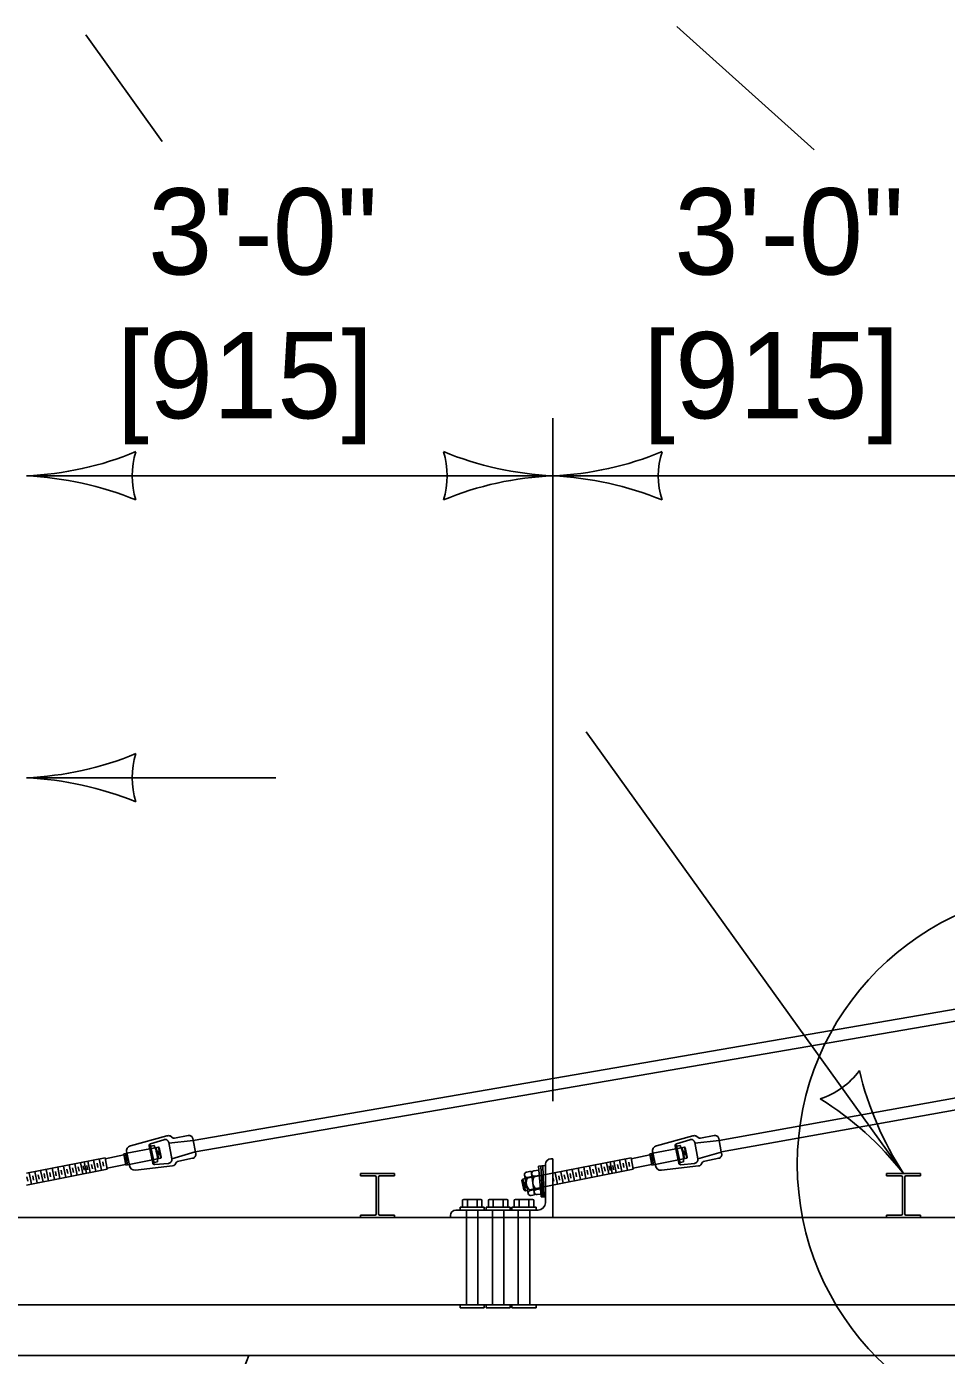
# Model space of a CAD drawing. Extents: x 49991.4 to 50021, y 49987.6 to 50011.4.
# Drawn here: x 50002.768 to 50003.408, y 49996.713 to 49997.638 of the extents above; entities that cross this region are included whole.
import ezdxf

# ---------------------------------------------------------------- set-up
doc = ezdxf.new("R2010")
doc.units = 0
for name, color, linetype in [('Level 1', 7, 'Continuous'), ('Level 2', 7, 'Continuous'), ('Level 3', 7, 'Continuous'), ('Level 4', 7, 'Continuous')]:
    doc.layers.add(name, color=color, linetype=linetype)

msp = doc.modelspace()

# ---------------------------------------------------------------- linework, layer by layer
at = {"layer": 'Level 1'}
for p, q in [((50002.8842, 49996.86275), (50006.12112, 49997.4208)), ((50002.88578, 49996.85474), (50006.12265, 49997.41281)), ((50003.25008, 49996.86273), (50006.12834, 49997.38128)), ((50003.25178, 49996.85474), (50006.1298, 49997.37361)), ((50002.86593, 49996.86597), (50002.84073, 49996.85901)), ((50002.85466, 49996.85945), (50002.85372, 49996.85927)), ((50002.85614, 49996.84702), (50002.85378, 49996.85897)), ((50002.85466, 49996.85945), (50002.85726, 49996.84691)), ((50002.86384, 49996.86331), (50002.85469, 49996.86047)), ((50002.85709, 49996.85931), (50002.85479, 49996.85886)), ((50002.86948, 49996.85002), (50002.86727, 49996.86126)), ((50002.87043, 49996.8644), (50002.86817, 49996.86592)), ((50002.88079, 49996.86617), (50002.87123, 49996.86428)), ((50002.88394, 49996.86406), (50002.88602, 49996.85355)), ((50003.23181, 49996.86595), (50003.20661, 49996.85898)), ((50003.22054, 49996.85943), (50003.2196, 49996.85925)), ((50003.22201, 49996.847), (50003.21965, 49996.85895)), ((50003.22054, 49996.85943), (50003.22314, 49996.84689)), ((50003.22971, 49996.86329), (50003.22057, 49996.86045)), ((50003.22296, 49996.85929), (50003.22066, 49996.85883)), ((50003.23536, 49996.85), (50003.23315, 49996.86124)), ((50003.23631, 49996.86438), (50003.23404, 49996.8659)), ((50003.24666, 49996.86615), (50003.2371, 49996.86426)), ((50003.24982, 49996.86404), (50003.25189, 49996.85352)), ((50002.7684, 49996.83992), (50002.82299, 49996.85071)), ((50002.81498, 49996.84913), (50002.81666, 49996.84126)), ((50002.81892, 49996.8499), (50002.82048, 49996.84202)), ((50002.82299, 49996.85071), (50002.82455, 49996.84282)), ((50002.83612, 49996.85268), (50002.82313, 49996.84999)), ((50002.83823, 49996.85385), (50002.83599, 49996.85341)), ((50002.83599, 49996.85341), (50002.83741, 49996.84561)), ((50002.83713, 49996.85077), (50002.83775, 49996.84828)), ((50002.8386, 49996.84585), (50002.83719, 49996.85364)), ((50002.8381, 49996.85449), (50002.83998, 49996.8453)), ((50002.83832, 49996.85101), (50002.8388, 49996.84862)), ((50002.8601, 49996.85817), (50002.85781, 49996.85771)), ((50002.85852, 49996.85786), (50002.86019, 49996.85012)), ((50002.86176, 49996.85042), (50002.85946, 49996.84997)), ((50002.85963, 49996.85563), (50002.86029, 49996.85257)), ((50002.86068, 49996.85778), (50002.8601, 49996.85817)), ((50002.86176, 49996.85042), (50002.8601, 49996.85817)), ((50002.86068, 49996.85778), (50002.86209, 49996.85123)), ((50002.86209, 49996.85123), (50002.86176, 49996.85042)), ((50002.88393, 49996.85039), (50002.87428, 49996.84838)), ((50003.1344, 49996.85004), (50003.13312, 49996.85004)), ((50003.13428, 49996.8399), (50003.18887, 49996.85069)), ((50003.1344, 49996.85004), (50003.1344, 49996.80924)), ((50003.18086, 49996.8491), (50003.18254, 49996.84124)), ((50003.1848, 49996.84988), (50003.18636, 49996.842)), ((50003.18887, 49996.85069), (50003.19042, 49996.8428)), ((50003.202, 49996.85266), (50003.18901, 49996.84997)), ((50003.2041, 49996.85383), (50003.20187, 49996.85338)), ((50003.20187, 49996.85338), (50003.20328, 49996.84559)), ((50003.20301, 49996.85075), (50003.20362, 49996.84826)), ((50003.20448, 49996.84583), (50003.20307, 49996.85362)), ((50003.20397, 49996.85447), (50003.20585, 49996.84527)), ((50003.2042, 49996.85098), (50003.20467, 49996.84859)), ((50003.22598, 49996.85815), (50003.22368, 49996.85769)), ((50003.2244, 49996.85783), (50003.22607, 49996.85009)), ((50003.22764, 49996.8504), (50003.22533, 49996.84995)), ((50003.2255, 49996.85561), (50003.22617, 49996.85255)), ((50003.22655, 49996.85776), (50003.22598, 49996.85815)), ((50003.22764, 49996.8504), (50003.22598, 49996.85815)), ((50003.22655, 49996.85776), (50003.22797, 49996.85121)), ((50003.22797, 49996.85121), (50003.22764, 49996.8504)), ((50003.24981, 49996.85037), (50003.24015, 49996.84836)), ((50002.7684, 49996.83173), (50002.82455, 49996.84282)), ((50002.77029, 49996.8403), (50002.77185, 49996.83241)), ((50002.77423, 49996.84108), (50002.77579, 49996.83319)), ((50002.77817, 49996.84185), (50002.77985, 49996.83399)), ((50002.78212, 49996.84263), (50002.78368, 49996.83475)), ((50002.78464, 49996.84053), (50002.78512, 49996.83751)), ((50002.78618, 49996.84344), (50002.78774, 49996.83555)), ((50002.78847, 49996.84128), (50002.78909, 49996.83818)), ((50002.79012, 49996.84421), (50002.79157, 49996.8363)), ((50002.79253, 49996.84209), (50002.793, 49996.83908)), ((50002.79407, 49996.84499), (50002.79563, 49996.83711)), ((50002.79636, 49996.84284), (50002.79707, 49996.83987)), ((50002.79801, 49996.84577), (50002.79957, 49996.83789)), ((50002.80042, 49996.84364), (50002.80104, 49996.84054)), ((50002.80196, 49996.84655), (50002.80352, 49996.83867)), ((50002.80425, 49996.84439), (50002.80495, 49996.84144)), ((50002.8059, 49996.84733), (50002.80758, 49996.83947)), ((50002.80783, 49996.8451), (50002.80844, 49996.842)), ((50002.80853, 49996.84785), (50002.80997, 49996.83994)), ((50002.81026, 49996.84534), (50002.81074, 49996.84233)), ((50002.81104, 49996.84835), (50002.81259, 49996.84046)), ((50002.81347, 49996.8461), (50002.81418, 49996.84313)), ((50002.81739, 49996.84699), (50002.818, 49996.84389)), ((50002.82145, 49996.84779), (50002.82192, 49996.84478)), ((50002.83732, 49996.84609), (50002.82441, 49996.84354)), ((50002.83981, 49996.84609), (50002.83741, 49996.84561)), ((50002.86994, 49996.84503), (50002.84408, 49996.84203)), ((50002.85726, 49996.84691), (50002.85625, 49996.84671)), ((50002.85944, 49996.84798), (50002.85713, 49996.84752)), ((50002.86709, 49996.84682), (50002.85758, 49996.84594)), ((50002.87149, 49996.8458), (50002.87272, 49996.84764)), ((50003.11621, 49996.84068), (50003.11946, 49996.84133)), ((50003.12166, 49996.82489), (50003.11946, 49996.84133)), ((50003.12127, 49996.84156), (50003.12475, 49996.84203)), ((50003.12449, 49996.84487), (50003.12919, 49996.84543)), ((50003.12449, 49996.84487), (50003.12645, 49996.82355)), ((50003.12611, 49996.84507), (50003.1273, 49996.82358)), ((50003.12757, 49996.84524), (50003.12822, 49996.8236)), ((50003.12932, 49996.84624), (50003.12932, 49996.8194)), ((50003.13428, 49996.83171), (50003.19042, 49996.8428)), ((50003.13617, 49996.84028), (50003.13772, 49996.83239)), ((50003.1401, 49996.84105), (50003.14166, 49996.83317)), ((50003.14405, 49996.84183), (50003.14573, 49996.83397)), ((50003.14799, 49996.84261), (50003.14955, 49996.83472)), ((50003.15052, 49996.84051), (50003.15099, 49996.83749)), ((50003.15206, 49996.84341), (50003.15361, 49996.83553)), ((50003.15434, 49996.84126), (50003.15496, 49996.83815)), ((50003.156, 49996.84419), (50003.15744, 49996.83628)), ((50003.15841, 49996.84207), (50003.15888, 49996.83905)), ((50003.15994, 49996.84497), (50003.1615, 49996.83709)), ((50003.16223, 49996.84282), (50003.16295, 49996.83985)), ((50003.16389, 49996.84575), (50003.16544, 49996.83786)), ((50003.16629, 49996.84362), (50003.16691, 49996.84051)), ((50003.16783, 49996.84653), (50003.16939, 49996.83865)), ((50003.17012, 49996.84437), (50003.17083, 49996.84141)), ((50003.17178, 49996.84731), (50003.17345, 49996.83945)), ((50003.17371, 49996.84508), (50003.17432, 49996.84198)), ((50003.17441, 49996.84783), (50003.17584, 49996.83992)), ((50003.17614, 49996.84532), (50003.17661, 49996.84231)), ((50003.17692, 49996.84833), (50003.17847, 49996.84044)), ((50003.17935, 49996.84608), (50003.18006, 49996.84311)), ((50003.18327, 49996.84697), (50003.18388, 49996.84387)), ((50003.18733, 49996.84777), (50003.1878, 49996.84476)), ((50003.2032, 49996.84607), (50003.19029, 49996.84352)), ((50003.20569, 49996.84607), (50003.20328, 49996.84559)), ((50003.23582, 49996.84501), (50003.20996, 49996.84201)), ((50003.22314, 49996.84689), (50003.22212, 49996.84669)), ((50003.22531, 49996.84796), (50003.22301, 49996.8475)), ((50003.23297, 49996.8468), (50003.22346, 49996.84592)), ((50003.23737, 49996.84578), (50003.2386, 49996.84762)), ((50002.76863, 49996.83737), (50002.76934, 49996.8344)), ((50002.77269, 49996.83817), (50002.77317, 49996.83515)), ((50002.77652, 49996.83892), (50002.77723, 49996.83595)), ((50002.78058, 49996.83973), (50002.7812, 49996.83662)), ((50003.02424, 49996.83972), (50003.00056, 49996.83972)), ((50003.00056, 49996.83812), (50003.00056, 49996.83972)), ((50003.0108, 49996.83812), (50003.00056, 49996.83812)), ((50003.0116, 49996.81164), (50003.0116, 49996.83732)), ((50003.0132, 49996.81164), (50003.0132, 49996.83732)), ((50003.02424, 49996.83812), (50003.014, 49996.83812)), ((50003.02424, 49996.83812), (50003.02424, 49996.83972)), ((50003.113, 49996.83495), (50003.11368, 49996.83595)), ((50003.11427, 49996.82849), (50003.113, 49996.83494)), ((50003.11368, 49996.83595), (50003.11524, 49996.83626)), ((50003.11368, 49996.83595), (50003.11542, 49996.82773)), ((50003.11466, 49996.82968), (50003.11371, 49996.83385)), ((50003.11735, 49996.82591), (50003.11477, 49996.83854)), ((50003.11576, 49996.82978), (50003.11506, 49996.83399)), ((50003.11692, 49996.83711), (50003.11995, 49996.83771)), ((50003.12176, 49996.83794), (50003.12509, 49996.83838)), ((50003.13451, 49996.83734), (50003.13522, 49996.83437)), ((50003.13857, 49996.83815), (50003.13904, 49996.83513)), ((50003.14239, 49996.8389), (50003.14311, 49996.83593)), ((50003.14646, 49996.8397), (50003.14707, 49996.8366)), ((50003.39024, 49996.83972), (50003.36656, 49996.83972)), ((50003.36656, 49996.83812), (50003.36656, 49996.83972)), ((50003.3768, 49996.83812), (50003.36656, 49996.83812)), ((50003.3776, 49996.81164), (50003.3776, 49996.83732)), ((50003.3792, 49996.81164), (50003.3792, 49996.83732)), ((50003.39024, 49996.83812), (50003.38, 49996.83812)), ((50003.39024, 49996.83812), (50003.39024, 49996.83972)), ((50003.07163, 49996.8166), (50003.07163, 49996.82149)), ((50003.07333, 49996.82177), (50003.08346, 49996.82177)), ((50003.07499, 49996.81659), (50003.07499, 49996.8215)), ((50003.08182, 49996.81659), (50003.08182, 49996.8215)), ((50003.08517, 49996.8166), (50003.08517, 49996.82149)), ((50003.08963, 49996.8166), (50003.08963, 49996.82149)), ((50003.09133, 49996.82177), (50003.10146, 49996.82177)), ((50003.09299, 49996.81659), (50003.09299, 49996.8215)), ((50003.09982, 49996.81659), (50003.09982, 49996.8215)), ((50003.10317, 49996.8166), (50003.10317, 49996.82149)), ((50003.10763, 49996.8166), (50003.10763, 49996.82149)), ((50003.10933, 49996.82177), (50003.11946, 49996.82177)), ((50003.11099, 49996.81659), (50003.11099, 49996.8215)), ((50003.11542, 49996.82773), (50003.11427, 49996.82849)), ((50003.11542, 49996.82773), (50003.11692, 49996.82803)), ((50003.11782, 49996.81659), (50003.11782, 49996.8215)), ((50003.11879, 49996.82805), (50003.12118, 49996.82852)), ((50003.1195, 49996.82447), (50003.12166, 49996.82489)), ((50003.12117, 49996.8166), (50003.12117, 49996.82149)), ((50003.12299, 49996.82876), (50003.12594, 49996.82916)), ((50003.12348, 49996.82514), (50003.12627, 49996.82551)), ((50003.12645, 49996.82355), (50003.12932, 49996.82363)), ((50003.12424, 49996.81432), (50003.067, 49996.81432)), ((50003.07001, 49996.81632), (50003.08679, 49996.81632)), ((50003.07001, 49996.81632), (50003.07001, 49996.81432)), ((50003.07001, 49996.81432), (50003.08679, 49996.81432)), ((50003.08679, 49996.81632), (50003.08679, 49996.81432)), ((50003.08801, 49996.81632), (50003.10479, 49996.81632)), ((50003.08801, 49996.81632), (50003.08801, 49996.81432)), ((50003.08801, 49996.81432), (50003.10479, 49996.81432)), ((50003.10479, 49996.81632), (50003.10479, 49996.81432)), ((50003.10601, 49996.81632), (50003.12279, 49996.81632)), ((50003.10601, 49996.81632), (50003.10601, 49996.81432)), ((50003.10601, 49996.81432), (50003.12279, 49996.81432)), ((50003.12279, 49996.81632), (50003.12279, 49996.81432)), ((50004.83228, 49996.80924), (50002.6464, 49996.80924)), ((50003.00056, 49996.80924), (50003.00056, 49996.81084)), ((50003.0108, 49996.81084), (50003.00056, 49996.81084)), ((50003.02424, 49996.81084), (50003.014, 49996.81084)), ((50003.02424, 49996.80924), (50003.02424, 49996.81084)), ((50003.0632, 49996.80924), (50003.0632, 49996.81052)), ((50003.1344, 49996.80924), (50003.0632, 49996.80924)), ((50003.3768, 49996.81084), (50003.36656, 49996.81084)), ((50003.36656, 49996.81084), (50003.36656, 49996.80924)), ((50003.39024, 49996.81084), (50003.38, 49996.81084)), ((50003.39024, 49996.80924), (50003.39024, 49996.81084)), ((50003.86643, 49996.74844), (50000.13627, 49996.74844)), ((50003.9076, 49996.71324), (50000.15294, 49996.71324))]:
    msp.add_line(p, q, dxfattribs=at)
msp.add_circle((50003.49532, 49996.84624), 0.19084, dxfattribs=at)
for centre, radius, start, end in [((50002.84143, 49996.85557), 0.0035, 101.46836, 197.94993), ((50002.85488, 49996.85933), 0.00116, 99.58417, 197.7734), ((50002.8368, 49996.84919), 0.02267, 356.92883, 26.50774), ((50002.86476, 49996.86096), 0.00252, 6.78065, 111.49404), ((50002.86698, 49996.86272), 0.00341, 69.60327, 107.90821), ((50002.87104, 49996.86575), 0.00148, 245.81175, 277.18979), ((50002.88141, 49996.86369), 0.00256, 8.29576, 104.05253), ((50003.2073, 49996.85555), 0.0035, 101.46836, 197.94993), ((50003.22076, 49996.85931), 0.00116, 99.58417, 197.7734), ((50003.20268, 49996.84917), 0.02267, 356.92883, 26.50774), ((50003.23064, 49996.86094), 0.00252, 6.78065, 111.49404), ((50003.23286, 49996.8627), 0.00341, 69.60327, 107.90821), ((50003.23692, 49996.86573), 0.00148, 245.81175, 277.18979), ((50003.24728, 49996.86367), 0.00256, 8.29576, 104.05253), ((50002.86678, 49996.84955), 0.00274, 276.48423, 9.91066), ((50002.88345, 49996.85297), 0.00263, 280.42161, 12.59648), ((50003.13312, 49996.84624), 0.0038, 90, 180), ((50003.23266, 49996.84953), 0.00274, 276.48423, 9.91066), ((50003.24933, 49996.85295), 0.00263, 280.42161, 12.59648), ((50002.84392, 49996.84604), 0.00401, 190.70039, 272.37573), ((50002.85749, 49996.84732), 0.00138, 192.45537, 273.81412), ((50002.86992, 49996.84701), 0.00198, 270.62889, 322.54343), ((50002.87428, 49996.84639), 0.002, 90.00489, 141.0233), ((50003.11656, 49996.8389), 0.00183, 101.17557, 281.17272), ((50003.12152, 49996.83975), 0.00183, 97.63348, 277.63063), ((50003.20979, 49996.84602), 0.00401, 190.70039, 272.37573), ((50003.22337, 49996.8473), 0.00138, 192.45537, 273.81412), ((50003.2358, 49996.84699), 0.00198, 270.62889, 322.54343), ((50003.24015, 49996.84637), 0.002, 90.00489, 141.0233), ((50003.0108, 49996.83732), 0.0008, 0, 90), ((50003.014, 49996.83732), 0.0008, 90, 180), ((50003.12279, 49996.83356), 0.00686, 148.88147, 233.6485), ((50003.12729, 49996.83401), 0.00679, 144.59653, 230.66757), ((50003.3768, 49996.83732), 0.0008, 0, 90), ((50003.38, 49996.83732), 0.0008, 90, 180), ((50003.11914, 49996.82626), 0.00183, 101.17557, 281.17272), ((50003.12323, 49996.82695), 0.00183, 97.63348, 277.63063), ((50003.067, 49996.81052), 0.0038, 90, 180), ((50003.12424, 49996.8194), 0.00508, 270, 0), ((50003.0108, 49996.81164), 0.0008, 270, 0), ((50003.014, 49996.81164), 0.0008, 180, 270), ((50003.3768, 49996.81164), 0.0008, 270, 0), ((50003.38, 49996.81164), 0.0008, 180, 270)]:
    msp.add_arc(centre, radius, start, end, dxfattribs=at)
for centre, major_axis, start_param, end_param in [((50003.07332, 49996.81966), (0.00339, 0), 1.056847, 2.094396), ((50003.0784, 49996.81332), (0.01355, 0), 1.315951, 1.825641), ((50003.08348, 49996.81966), (0.00339, 0), 1.047198, 2.084746), ((50003.09132, 49996.81966), (0.00339, 0), 1.056847, 2.094396), ((50003.0964, 49996.81332), (0.01355, 0), 1.315951, 1.825641), ((50003.10148, 49996.81966), (0.00339, 0), 1.047198, 2.084746), ((50003.10932, 49996.81966), (0.00339, 0), 1.056847, 2.094396), ((50003.1144, 49996.81332), (0.01355, 0), 1.315951, 1.825641), ((50003.11948, 49996.81966), (0.00339, 0), 1.047198, 2.084746), ((50003.07332, 49996.81843), (0.00339, 0), 4.188789, 5.226338), ((50003.0784, 49996.82477), (0.01355, 0), 4.457545, 4.967235), ((50003.08348, 49996.81843), (0.00339, 0), 4.198439, 5.235988), ((50003.09132, 49996.81843), (0.00339, 0), 4.188789, 5.226338), ((50003.0964, 49996.82477), (0.01355, 0), 4.457545, 4.967235), ((50003.10148, 49996.81843), (0.00339, 0), 4.198439, 5.235988), ((50003.10932, 49996.81843), (0.00339, 0), 4.188789, 5.226338), ((50003.1144, 49996.82477), (0.01355, 0), 4.457545, 4.967235), ((50003.11948, 49996.81843), (0.00339, 0), 4.198439, 5.235988)]:
    msp.add_ellipse(centre, major_axis=major_axis, ratio=0.623816, start_param=start_param, end_param=end_param, dxfattribs=at)
at = {"layer": 'Level 3'}
for p, q in [((50003.22069, 49997.63753), (50003.31634, 49997.55177)), ((50002.80952, 49997.63175), (50002.86281, 49997.55755)), ((50003.1344, 49996.89004), (50003.1344, 49997.36506)), ((50002.7684, 49997.32506), (50003.1344, 49997.32506)), ((50003.1344, 49997.32506), (50003.5004, 49997.32506)), ((50003.15774, 49997.14694), (50003.3784, 49996.83972)), ((50002.7684, 49997.11506), (50002.94184, 49997.11506)), ((50002.9231, 49996.71324), (50002.81609, 49996.44087))]:
    msp.add_line(p, q, dxfattribs=at)
for centre, radius, start, end in [((50002.75924, 49997.5472), 0.22232, 272.36048, 292.54399), ((50002.89661, 49997.32506), 0.05477, 162.13882, 197.86118), ((50003.00619, 49997.32506), 0.05477, 342.13882, 17.86118), ((50003.14589, 49997.55778), 0.233, 247.92284, 267.17269), ((50003.12524, 49997.5472), 0.22232, 272.36048, 292.54399), ((50003.26261, 49997.32506), 0.05477, 162.13882, 197.86118), ((50002.75691, 49997.09235), 0.233, 67.92284, 87.17269), ((50003.14356, 49997.10293), 0.22232, 92.36048, 112.54399), ((50003.12291, 49997.09235), 0.233, 67.92284, 87.17269), ((50002.75924, 49997.3372), 0.22232, 272.36048, 292.54399), ((50002.89661, 49997.11506), 0.05477, 162.13882, 197.86118), ((50002.75691, 49996.88235), 0.233, 67.92284, 87.17269), ((50003.3036, 49996.94386), 0.05477, 287.82673, 323.54909), ((50003.57412, 49996.96614), 0.233, 193.61075, 212.8606), ((50003.20332, 49996.7027), 0.22232, 38.04839, 58.2319)]:
    msp.add_arc(centre, radius, start, end, dxfattribs=at)
at = {"layer": 'Level 4'}
for p, q in [((50002.8842, 49996.86275), (50002.86735, 49996.86087)), ((50003.25008, 49996.86273), (50003.23322, 49996.86085)), ((50002.85781, 49996.85771), (50002.83823, 49996.85385)), ((50002.85946, 49996.84997), (50002.83981, 49996.84609)), ((50002.88578, 49996.85474), (50002.86947, 49996.85006)), ((50003.22368, 49996.85769), (50003.2041, 49996.85383)), ((50003.22533, 49996.84995), (50003.20569, 49996.84607)), ((50003.25166, 49996.85472), (50003.23535, 49996.85004)), ((50003.13428, 49996.8399), (50003.11636, 49996.83648)), ((50003.11834, 49996.82834), (50003.13428, 49996.83171)), ((50003.0744, 49996.74844), (50003.0744, 49996.81432)), ((50003.0824, 49996.74844), (50003.0824, 49996.81432)), ((50003.0924, 49996.74844), (50003.0924, 49996.81432)), ((50003.1004, 49996.74844), (50003.1004, 49996.81432)), ((50003.1104, 49996.74844), (50003.1104, 49996.81432)), ((50003.1184, 49996.74844), (50003.1184, 49996.81432)), ((50003.07001, 49996.74645), (50003.07001, 49996.74844)), ((50003.07001, 49996.74844), (50003.08679, 49996.74844)), ((50003.08679, 49996.74645), (50003.08679, 49996.74844)), ((50003.08801, 49996.74645), (50003.08801, 49996.74844)), ((50003.08801, 49996.74844), (50003.10479, 49996.74844)), ((50003.10479, 49996.74645), (50003.10479, 49996.74844)), ((50003.10601, 49996.74645), (50003.10601, 49996.74844)), ((50003.10601, 49996.74844), (50003.12279, 49996.74844)), ((50003.12279, 49996.74645), (50003.12279, 49996.74844)), ((50003.07001, 49996.74645), (50003.08679, 49996.74645)), ((50003.08801, 49996.74645), (50003.10479, 49996.74645)), ((50003.10601, 49996.74645), (50003.12279, 49996.74645))]:
    msp.add_line(p, q, dxfattribs=at)

# ---------------------------------------------------------------- texts
at = {"layer": 'Level 2'}
for s, p in [('3\'-0"', (50002.85294, 49997.46506)), ('3\'-0"', (50003.21894, 49997.46506)), ('[915]', (50002.83118, 49997.36506)), ('[915]', (50003.19718, 49997.36506))]:
    msp.add_text(s, height=0.06, dxfattribs=at).set_placement(p)

doc.saveas('drawing.dxf')
